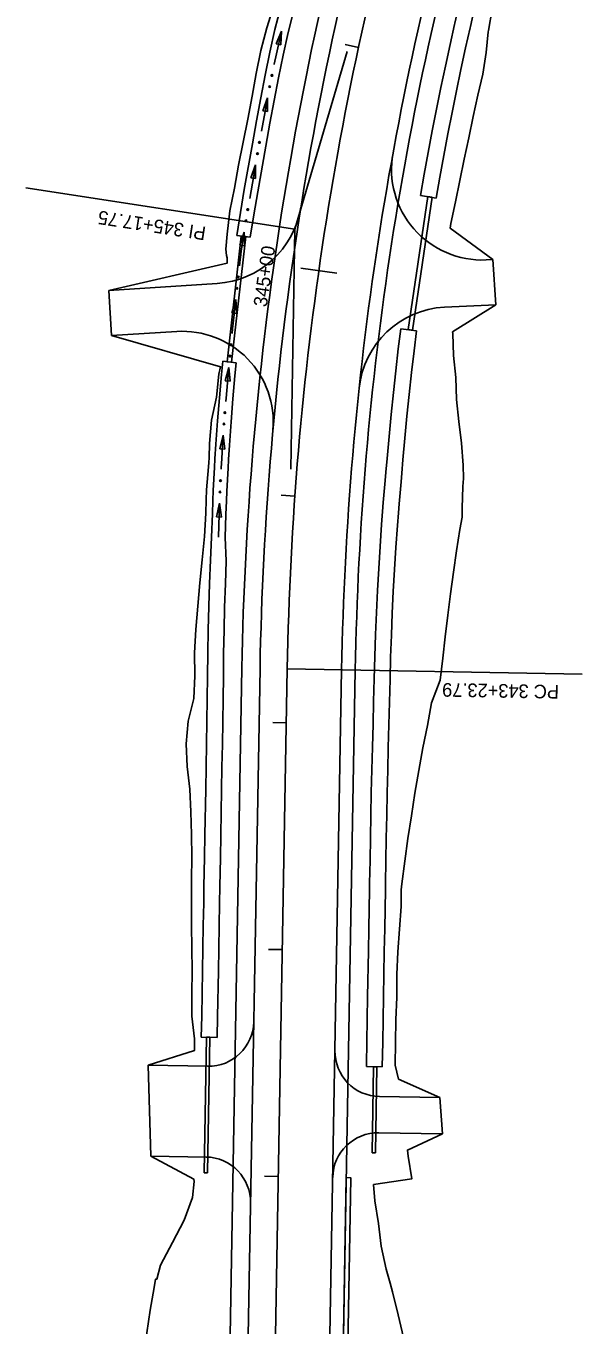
# Model space of a CAD drawing. Extents: x 948761 to 996004, y 1858548 to 1925175.
# Drawn here: x 960871 to 961116, y 1905104 to 1905677 of the extents above; entities that cross this region are included whole.
import ezdxf

# ---------------------------------------------------------------- set-up
doc = ezdxf.new("R2010")
doc.units = 0
for name, color, linetype in [('62', 7, 'Continuous'), ('R_Drainage', 7, 'Continuous'), ('R_Horz Alg', 7, 'Continuous'), ('R_Horz Alg Annot', 7, 'Continuous'), ('R_Proposed Const Limits', 7, 'Continuous'), ('R_Proposed Road', 7, 'Continuous')]:
    doc.layers.add(name, color=color, linetype=linetype)

msp = doc.modelspace()

# ---------------------------------------------------------------- linework, layer by layer
at = {"layer": '62'}
for p, q in [((960983.74, 1905674.94), (960981.4, 1905669.31)), ((960983.47, 1905668.85), (960983.74, 1905674.94)), ((960981.4, 1905669.31), (960983.47, 1905668.85)), ((960977.63, 1905645.53), (960975.49, 1905639.83)), ((960977.57, 1905639.44), (960977.63, 1905645.53)), ((960975.49, 1905639.83), (960977.57, 1905639.44)), ((960972.33, 1905615.97), (960970.24, 1905610.24)), ((960972.32, 1905609.87), (960972.33, 1905615.97)), ((960970.24, 1905610.24), (960972.32, 1905609.87)), ((961045.08, 1905602.51), (961051.98, 1905601.31)), ((960969.98, 1905584.02), (960964.04, 1905584.87)), ((960967.3, 1905586.35), (960965.36, 1905580.58)), ((960967.45, 1905580.26), (960967.3, 1905586.35)), ((960965.36, 1905580.58), (960967.45, 1905580.26)), ((960963.59, 1905556.55), (960961.89, 1905550.7)), ((960963.99, 1905550.47), (960963.59, 1905556.55)), ((960961.89, 1905550.7), (960963.99, 1905550.47)), ((961035.25, 1905534.85), (961036.35, 1905543.67)), ((961036.35, 1905543.67), (961043.29, 1905542.81)), ((961042.2, 1905534.01), (961043.29, 1905542.81)), ((961034.13, 1905525.19), (961035.25, 1905534.85)), ((961041.08, 1905524.4), (961042.2, 1905534.01)), ((960963.8, 1905528.71), (960957.83, 1905529.37)), ((960960.58, 1905526.66), (960958.94, 1905520.8)), ((960961.04, 1905520.59), (960960.58, 1905526.66)), ((961033.06, 1905515.52), (961034.13, 1905525.19)), ((961040.03, 1905514.78), (961041.08, 1905524.4)), ((960958.94, 1905520.8), (960961.04, 1905520.59)), ((961032.07, 1905505.84), (961033.06, 1905515.52)), ((961039.04, 1905505.15), (961040.03, 1905514.78)), ((961031.15, 1905496.16), (961032.07, 1905505.84)), ((961038.12, 1905495.52), (961039.04, 1905505.15)), ((960958.09, 1905496.73), (960956.62, 1905490.82)), ((960958.73, 1905490.67), (960958.09, 1905496.73)), ((961030.29, 1905486.48), (961031.15, 1905496.16)), ((960956.62, 1905490.82), (960958.73, 1905490.67)), ((961037.26, 1905485.88), (961038.12, 1905495.52)), ((961029.79, 1905480.46), (961030.29, 1905486.48)), ((961036.78, 1905480.01), (961037.26, 1905485.88)), ((961029.46, 1905476.82), (961029.79, 1905480.46)), ((961036.44, 1905476.21), (961036.78, 1905480)), ((961036.78, 1905480), (961036.78, 1905480.01)), ((961028.64, 1905467.13), (961029.46, 1905476.82)), ((961035.62, 1905466.56), (961036.44, 1905476.21)), ((961028.32, 1905463.06), (961028.64, 1905467.13)), ((960956.43, 1905466.74), (960955.14, 1905460.78)), ((960957.26, 1905460.7), (960956.43, 1905466.74)), ((961027.89, 1905457.43), (961028.32, 1905463.06)), ((961034.88, 1905456.92), (961035.3, 1905462.52)), ((961035.3, 1905462.52), (961035.62, 1905466.56)), ((960955.14, 1905460.78), (960957.26, 1905460.7)), ((961027.21, 1905447.72), (961027.89, 1905457.43)), ((961034.2, 1905447.26), (961034.88, 1905456.92)), ((961026.6, 1905438.01), (961027.21, 1905447.72)), ((961033.59, 1905437.6), (961034.2, 1905447.26)), ((961026.06, 1905428.3), (961026.6, 1905438.01)), ((961033.05, 1905427.93), (961033.59, 1905437.6)), ((961025.59, 1905418.58), (961026.06, 1905428.3)), ((961032.59, 1905418.27), (961033.05, 1905427.93)), ((961025.2, 1905408.85), (961025.59, 1905418.58)), ((961032.19, 1905408.59), (961032.59, 1905418.27)), ((961024.87, 1905399.13), (961025.2, 1905408.85)), ((961031.86, 1905398.91), (961032.19, 1905408.59)), ((961024.6, 1905389.3), (961024.87, 1905399.13)), ((961031.6, 1905389.12), (961031.86, 1905398.91)), ((961024.35, 1905379.3), (961024.6, 1905389.3)), ((961031.34, 1905379.12), (961031.6, 1905389.12)), ((961024.09, 1905369.3), (961024.35, 1905379.3)), ((961031.09, 1905369.12), (961031.34, 1905379.12)), ((961023.84, 1905359.3), (961024.09, 1905369.3)), ((961030.84, 1905359.13), (961031.09, 1905369.12)), ((961023.6, 1905349.3), (961023.84, 1905359.3)), ((961030.59, 1905349.13), (961030.84, 1905359.13)), ((961023.6, 1905349.3), (961023.35, 1905339.3)), ((961030.59, 1905349.13), (961030.35, 1905339.14)), ((961023.35, 1905339.3), (961023.13, 1905329.29)), ((961030.35, 1905339.14), (961030.13, 1905329.15)), ((961023.13, 1905329.29), (961022.96, 1905319.28)), ((961030.13, 1905329.15), (961029.96, 1905319.16)), ((961022.78, 1905309.28), (961022.96, 1905319.28)), ((961029.78, 1905309.16), (961029.96, 1905319.16)), ((961022.6, 1905299.29), (961022.78, 1905309.28)), ((961029.6, 1905299.16), (961029.78, 1905309.16)), ((961022.56, 1905296.53), (961022.25, 1905279.29)), ((961022.6, 1905299.29), (961022.56, 1905296.54)), ((961022.56, 1905296.54), (961022.56, 1905296.53)), ((961029.56, 1905296.47), (961029.25, 1905279.17)), ((961029.6, 1905299.16), (961029.56, 1905296.48)), ((961029.56, 1905296.48), (961029.56, 1905296.47)), ((961022.07, 1905269.29), (961022.25, 1905279.29)), ((961029.07, 1905269.17), (961029.25, 1905279.17)), ((961021.72, 1905249.29), (961022.07, 1905269.29)), ((961028.72, 1905249.17), (961029.07, 1905269.17)), ((961021.54, 1905239.29), (961021.72, 1905249.29)), ((961028.54, 1905239.17), (961028.72, 1905249.17)), ((961021.37, 1905229.3), (961021.54, 1905239.29)), ((961028.37, 1905229.17), (961028.54, 1905239.17)), ((960948.39, 1905231.41), (960955.39, 1905231.28)), ((961021.19, 1905219.3), (961021.37, 1905229.3)), ((961028.17, 1905218.28), (961028.37, 1905229.17)), ((961021.18, 1905218.4), (961021.19, 1905219.3)), ((961021.18, 1905218.4), (961028.17, 1905218.28))]:
    msp.add_line(p, q, dxfattribs=at)
for points in [[(961045.08, 1905602.51), (961046.7, 1905611.8), (961048.43, 1905621.37), (961050.23, 1905630.93), (961052.1, 1905640.47), (961054.03, 1905650.01), (961056.03, 1905659.52), (961058.09, 1905669.03), (961060.08, 1905677.88), (961060.21, 1905678.49), (961062.31, 1905687.98), (961064.48, 1905697.46), (961066.72, 1905706.93), (961067.3, 1905709.27)], [(960964.04, 1905584.87), (960965.64, 1905594.93), (960967.35, 1905605.06), (960970.92, 1905625.24), (960972.69, 1905635.34), (960974.56, 1905645.44), (960976.52, 1905655.52), (960978.59, 1905665.6), (960980.83, 1905675.67), (960983.38, 1905685.62), (960985.53, 1905694.57), (960985.53, 1905694.61), (960985.8, 1905695.63), (960988.48, 1905705.51), (960989.03, 1905707.59)], [(960969.98, 1905584.02), (960971.57, 1905593.96), (960973.27, 1905604.04), (960976.83, 1905624.2), (960978.59, 1905634.28), (960980.45, 1905644.32), (960982.4, 1905654.35), (960984.46, 1905664.34), (960986.66, 1905674.27), (960989.2, 1905684.17), (960991.44, 1905693.48), (960991.59, 1905694.07), (960994.28, 1905703.96), (960994.85, 1905706.09)], [(961051.98, 1905601.31), (961053.59, 1905610.58), (961055.32, 1905620.1), (961057.11, 1905629.61), (961058.96, 1905639.11), (961060.89, 1905648.59), (961062.87, 1905658.06), (961064.93, 1905667.52), (961066.92, 1905676.37), (961067.05, 1905676.99), (961069.14, 1905686.44), (961071.3, 1905695.87), (961073.53, 1905705.29), (961074.1, 1905707.61)], [(960980.56, 1905660.28), (960981.52, 1905664.97), (960983.74, 1905674.94)], [(960980.55, 1905660.24), (960980.56, 1905660.28)], [(960974.93, 1905630.78), (960975.64, 1905634.81), (960977.51, 1905644.88), (960977.63, 1905645.53)], [(960974.93, 1905630.74), (960974.93, 1905630.78)], [(960969.74, 1905601.19), (960970.31, 1905604.55), (960972.09, 1905614.63), (960972.33, 1905615.97)], [(960969.74, 1905601.15), (960969.74, 1905601.19)], [(960965.24, 1905571.5), (960965.52, 1905574.19), (960965.64, 1905575.07), (960966.01, 1905577.84), (960966.99, 1905584.33), (960967.31, 1905586.35)], [(960965.23, 1905571.46), (960965.24, 1905571.5)], [(960962, 1905541.63), (960962.18, 1905543.64), (960963.29, 1905553.82), (960963.6, 1905556.55)], [(960961.99, 1905541.6), (960962, 1905541.63)], [(960948.39, 1905231.41), (960948.56, 1905240.58), (960948.91, 1905260.58), (960949.09, 1905270.58), (960949.26, 1905280.58), (960949.44, 1905290.58), (960949.57, 1905297.83), (960949.57, 1905297.84), (960949.79, 1905310.57), (960949.97, 1905320.57), (960950.32, 1905340.57), (960950.5, 1905350.57), (960950.68, 1905360.57), (960950.85, 1905370.56), (960951.02, 1905380.55), (960951.11, 1905390.54), (960951.23, 1905400.69), (960951.41, 1905410.94), (960951.66, 1905421.18), (960951.98, 1905431.42), (960952.38, 1905441.67), (960952.94, 1905451.87), (960953.25, 1905462.08), (960953.48, 1905468.03), (960953.66, 1905472.34), (960954.17, 1905482.58), (960954.39, 1905486.38), (960954.39, 1905486.39), (960954.81, 1905492.84), (960955.52, 1905503.07), (960956.35, 1905513.31), (960957.26, 1905523.53), (960957.83, 1905529.37)], [(960959.38, 1905441.42), (960958.93, 1905451.62), (960959.25, 1905461.87), (960959.47, 1905467.79), (960959.66, 1905472.06), (960960.16, 1905482.26), (960960.39, 1905486.12), (960960.8, 1905492.44), (960961.51, 1905502.62), (960962.33, 1905512.8), (960963.23, 1905522.97), (960963.8, 1905528.71)], [(960959.23, 1905511.72), (960959.34, 1905513.05), (960960.24, 1905523.25), (960960.58, 1905526.66)], [(960959.23, 1905511.69), (960959.23, 1905511.72)], [(960957.14, 1905481.76), (960957.17, 1905482.42), (960957.39, 1905486.29), (960957.39, 1905486.29), (960957.8, 1905492.64), (960958.09, 1905496.73)], [(960957.13, 1905481.72), (960957.14, 1905481.76)], [(960955.94, 1905451.75), (960956.25, 1905461.97), (960956.43, 1905466.74)], [(960955.39, 1905231.28), (960955.55, 1905240.46), (960955.91, 1905260.46), (960956.08, 1905270.46), (960956.26, 1905280.45), (960956.44, 1905290.45), (960956.57, 1905297.77), (960956.57, 1905297.78), (960956.79, 1905310.45), (960956.97, 1905320.45), (960957.32, 1905340.45), (960957.5, 1905350.44), (960957.67, 1905360.44), (960957.85, 1905370.44), (960958.02, 1905380.46), (960958.11, 1905390.47), (960958.23, 1905400.59), (960958.41, 1905410.79), (960958.66, 1905420.98), (960958.98, 1905431.18), (960959.37, 1905441.35), (960959.38, 1905441.42)]]:
    msp.add_lwpolyline(points, dxfattribs=at)
for centre in [(960978.55, 1905650.45), (960979.51, 1905655.37), (960974.03, 1905625.83), (960973.16, 1905620.9), (960968.87, 1905596.24), (960968.07, 1905591.3), (960964.67, 1905566.51), (960964.12, 1905561.53), (960961.5, 1905536.64), (960961.04, 1905531.65), (960958.4, 1905501.73), (960958.79, 1905506.72), (960956.85, 1905476.75), (960956.6, 1905471.74)]:
    msp.add_circle(centre, 0.375, dxfattribs=at)
at = {"layer": 'R_Drainage'}
for p, q in [((961048.22, 1905601.94), (961039.52, 1905543.37)), ((961041.5, 1905543.08), (961050.2, 1905601.65)), ((961050.2, 1905601.65), (961048.22, 1905601.94)), ((960967.98, 1905584.33), (960965.99, 1905584.56)), ((961039.52, 1905543.37), (961041.5, 1905543.08)), ((960961.75, 1905528.93), (960959.76, 1905529.15)), ((960960.01, 1905529.12), (960961.5, 1905528.96)), ((960950.64, 1905231.37), (960949.58, 1905171.6)), ((960952.14, 1905231.35), (960950.64, 1905231.37)), ((960951.08, 1905171.58), (960952.14, 1905231.35)), ((961024.32, 1905218.34), (961023.75, 1905180.41)), ((961025.82, 1905218.32), (961024.32, 1905218.34)), ((961025.25, 1905180.39), (961025.82, 1905218.32)), ((961023.75, 1905180.41), (961025.25, 1905180.39)), ((960949.58, 1905171.6), (960951.08, 1905171.58))]:
    msp.add_line(p, q, dxfattribs=at)
msp.add_lwpolyline([(960961.75, 1905528.93), (960967.98, 1905584.33), (960965.99, 1905584.56), (960959.76, 1905529.15)], close=True, dxfattribs=at)
at = {"layer": 'R_Horz Alg'}
msp.add_line((960973.94, 1904695.88), (960986.27, 1905393.73), dxfattribs=at)
msp.add_arc((962418.44, 1905368.43), 1432.39, 163.56518, 178.98802, dxfattribs=at)
at = {"layer": 'R_Horz Alg Annot'}
for q in [(961012.76, 1905665.87), (960987.82, 1905481.75)]:
    msp.add_line((960989.69, 1905587.66), q, dxfattribs=at)
for points in [[(961011.79, 1905668.98), (961017.66, 1905667.72)], [(960989.69, 1905587.66), (960871.08, 1905605.86)], [(960992.27, 1905570.4), (961008.12, 1905568.16)], [(960983.65, 1905470.28), (960989.64, 1905469.86)], [(960986.27, 1905393.73), (961116.25, 1905391.43)], [(960979.85, 1905370.05), (960985.85, 1905369.95)], [(960978.08, 1905270.07), (960984.08, 1905269.96)], [(960976.32, 1905170.08), (960982.31, 1905169.98)]]:
    msp.add_lwpolyline(points, dxfattribs=at)
at = {"layer": 'R_Proposed Const Limits'}
for points in [[(960907.55, 1905560.62), (960959.78, 1905572.57), (960959.84, 1905574.99), (960959.43, 1905575.95), (960959.23, 1905578.82), (960959.8, 1905585.4), (960960.94, 1905595.64), (960962.97, 1905605.74), (960964.85, 1905615.86), (960966.86, 1905625.96), (960968.83, 1905636.07), (960970.77, 1905646.17), (960972.63, 1905656.29), (960974.65, 1905666.39), (960977.33, 1905676.34), (960980.38, 1905686.2), (960983.07, 1905695.46), (960983.28, 1905696.08), (960983.28, 1905696.08), (960986.48, 1905705.89), (960987.95, 1905710.39), (960985.67, 1905711.7), (960964.54, 1905724.31)], [(961076.88, 1905574.16), (961058.15, 1905588.04), (961058.46, 1905590.17), (961060.42, 1905599.6), (961062.37, 1905609.02), (961064.3, 1905618.44), (961066.27, 1905627.85), (961068.25, 1905637.26), (961070.29, 1905646.65), (961072.5, 1905656.01), (961073.93, 1905665.53), (961074.85, 1905674.55), (961074.85, 1905674.55), (961074.94, 1905675.16), (961076.7, 1905684.63), (961078.88, 1905694), (961081.05, 1905703.38), (961082.23, 1905708.07), (961106.26, 1905710.39)], [(961053.53, 1905204.72), (961035.35, 1905212.9), (961033.79, 1905219.07), (961034.07, 1905229.07), (961034.17, 1905239.07), (961034.55, 1905249.07), (961034.66, 1905259.07), (961035.02, 1905269.06), (961035.75, 1905279.05), (961036.46, 1905289.04), (961036.53, 1905296.32), (961036.53, 1905296.33), (961036.81, 1905299.04), (961038.17, 1905309.01), (961039.43, 1905318.99), (961041.02, 1905328.97), (961042.49, 1905338.94), (961044.26, 1905348.91), (961046.05, 1905358.88), (961048.12, 1905368.85), (961049.87, 1905378.82), (961053.72, 1905388.75), (961054.81, 1905398.44), (961055.92, 1905407.93), (961057.07, 1905417.41), (961058.21, 1905426.88), (961059.58, 1905436.33), (961060.96, 1905445.76), (961062.36, 1905455.19), (961063.39, 1905460.64), (961063.43, 1905464.62), (961063.7, 1905474.11), (961064.01, 1905477.69), (961064.01, 1905477.69), (961063.89, 1905483.62), (961063.15, 1905493.21), (961061.94, 1905502.88), (961060.84, 1905512.57), (961060.62, 1905522.19), (961059.56, 1905531.92), (961059.32, 1905541.59), (961059.2, 1905542.28), (961078.24, 1905554.2)], [(960948.74, 1905441.87), (960949.81, 1905452.1), (960950.38, 1905462.35), (960950.47, 1905468.32), (960950.74, 1905472.62), (960951.49, 1905482.86), (960951.65, 1905484.8), (960951.81, 1905486.74), (960952.04, 1905493.13), (960952.81, 1905503.37), (960955.13, 1905513.47), (960956.17, 1905523.68), (960956.88, 1905526.92), (960908.82, 1905540.66)], [(960924.91, 1905219), (960945.31, 1905225.43), (960945.37, 1905230.64), (960944.15, 1905240.66), (960944.22, 1905250.66), (960944.32, 1905260.66), (960944.14, 1905270.67), (960944, 1905280.67), (960944.1, 1905290.67), (960944.1, 1905297.96), (960944.11, 1905299.32), (960944.12, 1905300.67), (960944.17, 1905310.67), (960943.99, 1905320.68), (960943.79, 1905330.68), (960943.38, 1905340.69), (960942.13, 1905350.72), (960941.72, 1905360.72), (960942.6, 1905370.71), (960945.11, 1905380.67), (960945.54, 1905390.66), (960945.36, 1905400.84), (960945.99, 1905411.12), (960946.91, 1905421.37), (960947.71, 1905431.63), (960948.74, 1905441.87)], [(961037.56, 1905098.99), (961035.2, 1905109.03), (961032.66, 1905119.08), (961031.64, 1905122.88), (961031.64, 1905122.89), (961031.59, 1905122.89), (961029.89, 1905129.13), (961027.73, 1905139.17), (961026.56, 1905149.19), (961024.93, 1905159.22), (961024.31, 1905166.41), (961041.25, 1905168.94), (961039.59, 1905178.97), (961039.27, 1905181.61), (961054.76, 1905188.7)], [(960871.71, 1905060.63), (960920.71, 1905072), (960920.6, 1905081.05), (960923.03, 1905091.01), (960924.37, 1905100.99), (960925.82, 1905110.97), (960927.57, 1905120.94), (960928.21, 1905124.71), (960928.68, 1905124.71), (960928.83, 1905124.71), (960930.45, 1905130.89), (960935.7, 1905140.8), (960940.79, 1905150.71), (960944.49, 1905160.64), (960945.18, 1905167.8), (960945.05, 1905168.82), (960926.09, 1905178.97)]]:
    msp.add_lwpolyline(points, dxfattribs=at)
at = {"layer": 'R_Proposed Road'}
for p, q in [((961073.94, 1905574.04), (961076.88, 1905574.16)), ((961078.24, 1905554.2), (961076.88, 1905574.16)), ((960907.55, 1905560.62), (960955.33, 1905563.66)), ((960908.82, 1905540.66), (960907.55, 1905560.62)), ((961055.63, 1905553.25), (961078.24, 1905554.2)), ((960908.82, 1905540.66), (960937.58, 1905542.49)), ((960953.94, 1904696.23), (960966.27, 1905394.08)), ((960961.94, 1904696.09), (960974.27, 1905393.94)), ((960997.94, 1904695.46), (961010.26, 1905393.31)), ((961003.93, 1904695.35), (961016.26, 1905393.2)), ((960924.91, 1905219), (960951.17, 1905218.53)), ((960924.91, 1905219), (960926.09, 1905178.97)), ((961053.53, 1905204.72), (961026.94, 1905205.19)), ((961054.76, 1905188.7), (961053.53, 1905204.72)), ((961054.76, 1905188.7), (961026.66, 1905189.2)), ((960926.09, 1905178.97), (960950.46, 1905178.54))]:
    msp.add_line(p, q, dxfattribs=at)
msp.add_lwpolyline([(961008.51, 1904954.48), (961010.51, 1904954.45), (961014.31, 1905169.41), (961012.31, 1905169.45)], close=True, dxfattribs=at)
for centre, radius, start, end in [((962418.44, 1905368.43), 1452.39, 163.56518, 178.98802), ((962418.44, 1905368.43), 1444.39, 163.56518, 178.98802), ((962418.44, 1905368.43), 1408.39, 163.56518, 178.98802), ((962418.44, 1905368.43), 1402.39, 163.56518, 178.98802), ((961072.26, 1905614), 40, 169.6618, 272.4062), ((960952.79, 1905603.58), 40, 273.6403, 350.8852), ((961057.73, 1905513.29), 40, 93.0173, 173.9233), ((960940.12, 1905502.57), 40, 354.8153, 93.6403), ((960951.52, 1905238.53), 20, 268.988, 358.988), ((961027.3, 1905225.19), 20, 178.988, 268.988), ((961026.31, 1905169.2), 20, 88.988, 178.988), ((960950.11, 1905158.54), 20, 358.988, 88.988)]:
    msp.add_arc(centre, radius, start, end, dxfattribs=at)

# ---------------------------------------------------------------- texts
at = {"layer": 'R_Horz Alg'}
msp.add_text('+', height=1, rotation=88.988, dxfattribs=at).set_placement((960986.77, 1905393.72))
at = {"layer": 'R_Horz Alg Annot'}
for s, rotation, p in [('PI 345+17.75', 171.2766, (960950.75, 1905588.57)), ('345+00', 81.9396, (960977.26, 1905553.08)), ('PC 343+23.79', 178.988, (961106.16, 1905386.61))]:
    msp.add_text(s, height=6, rotation=rotation, dxfattribs=at).set_placement(p)

doc.saveas('drawing.dxf')
